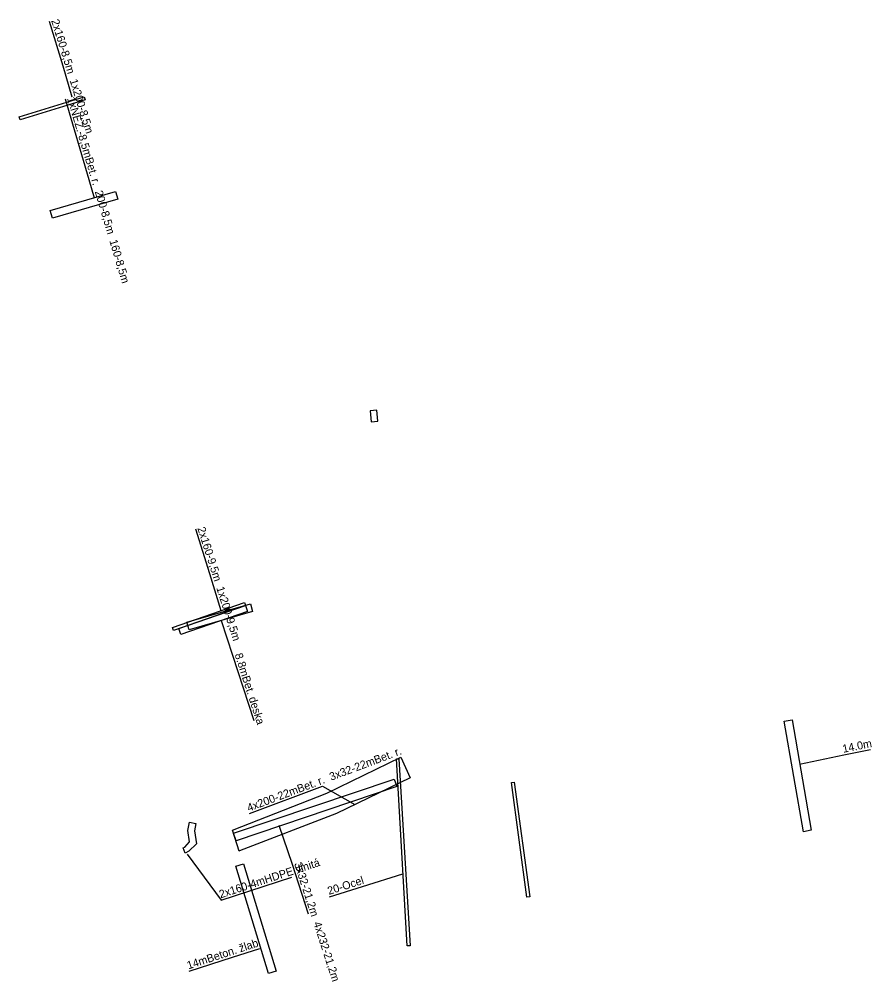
# Model space of a CAD drawing. Extents: x -740632 to -740525, y -1046807 to -1046687.
import ezdxf

# ---------------------------------------------------------------- set-up
doc = ezdxf.new("R2010")
doc.units = 0
for name, color, linetype in [('Chránička', 7, 'Continuous'), ('ST_CHRANICKA_POPIS', 7, 'Continuous'), ('ST_OBECNA_STAVBA', 7, 'Continuous')]:
    doc.layers.add(name, color=color, linetype=linetype)

msp = doc.modelspace()

# ---------------------------------------------------------------- linework, layer by layer
at = {"layer": 'Chránička'}
for points in [[(-740631.59, -1046699.489), (-740631.704, -1046699.105), (-740623.576, -1046696.612), (-740623.463, -1046696.994), (-740631.59, -1046699.489)], [(-740627.552, -1046711.796), (-740627.832, -1046710.836), (-740619.672, -1046708.458), (-740619.392, -1046709.418), (-740627.552, -1046711.796)], [(-740612.405, -1046763.312), (-740612.537, -1046762.934), (-740603.563, -1046759.817), (-740603.431, -1046760.195), (-740612.405, -1046763.312)], [(-740611.492, -1046763.814), (-740611.752, -1046763.058), (-740603.431, -1046760.195), (-740603.171, -1046760.951), (-740611.492, -1046763.814)], [(-740610.464, -1046763.249), (-740610.744, -1046762.289), (-740602.808, -1046759.977), (-740602.528, -1046760.937), (-740610.464, -1046763.249)], [(-740532.699, -1046788.285), (-740533.685, -1046788.457), (-740536.083, -1046774.664), (-740535.097, -1046774.492), (-740532.699, -1046788.285)], [(-740604.166, -1046790.844), (-740604.208, -1046790.886), (-740605.046, -1046788.265), (-740593.276, -1046783.655), (-740583.992, -1046779.129), (-740582.839, -1046781.729), (-740592.06, -1046786.171), (-740604.166, -1046790.844)], [(-740583.227, -1046802.737), (-740584.57, -1046779.371), (-740584.257, -1046779.365), (-740582.825, -1046802.71), (-740583.227, -1046802.737)], [(-740604.603, -1046789.596), (-740604.923, -1046788.648), (-740584.832, -1046781.882), (-740584.512, -1046782.83), (-740604.603, -1046789.596)], [(-740569.832, -1046782.28), (-740567.877, -1046796.585), (-740568.273, -1046796.643), (-740570.159, -1046782.321), (-740569.832, -1046782.28)], [(-740610.425, -1046787.274), (-740609.641, -1046787.429), (-740609.817, -1046788.342), (-740609.569, -1046789.974), (-740610.506, -1046790.892), (-740610.946, -1046791.122), (-740611.215, -1046790.485), (-740610.988, -1046790.389), (-740610.414, -1046789.724), (-740610.626, -1046788.32), (-740610.425, -1046787.274)], [(-740604.637, -1046792.779), (-740603.681, -1046792.487), (-740599.604, -1046805.88), (-740600.56, -1046806.172), (-740604.637, -1046792.779)]]:
    msp.add_lwpolyline(points, close=True, dxfattribs=at)
at = {"layer": 'ST_CHRANICKA_POPIS'}
for points in [[(-740627.959, -1046687.174), (-740626.237, -1046692.748), (-740625.118, -1046696.607)], [(-740625.977, -1046696.869), (-740622.989, -1046706.933), (-740622.358, -1046709.227)], [(-740609.687, -1046750.621), (-740607.921, -1046756.181), (-740606.517, -1046760.832)], [(-740606.464, -1046762.06), (-740605.032, -1046766.396), (-740602.402, -1046774.562)], [(-740534.161, -1046780.003), (-740528.652, -1046778.852), (-740525.289, -1046778.171)], [(-740602.922, -1046786.205), (-740593.799, -1046782.777), (-740589.756, -1046785.06)], [(-740599.248, -1046787.628), (-740597.593, -1046792.519), (-740595.586, -1046798.723)], [(-740610.711, -1046791.288), (-740606.461, -1046797.031), (-740597.653, -1046794.162)], [(-740592.922, -1046796.606), (-740588.804, -1046795.288), (-740583.771, -1046793.712)], [(-740610.479, -1046805.906), (-740605.065, -1046804.134), (-740601.644, -1046803.051)]]:
    msp.add_lwpolyline(points, dxfattribs=at)
at = {"layer": 'ST_OBECNA_STAVBA'}
msp.add_lwpolyline([(-740587.835, -1046735.867), (-740587.715, -1046737.233), (-740586.871, -1046737.153), (-740586.992, -1046735.787), (-740587.835, -1046735.867)], dxfattribs=at)

# ---------------------------------------------------------------- texts
at = {"layer": 'ST_CHRANICKA_POPIS'}
for s, rotation, p in [('2x160-8,5m  1x200-8,5m', 287.16939, (-740627.72, -1046687.101)), ('1xNEZ.-8,5mBet. r.  200-8,5m  160-8,5m', 286.53484, (-740625.737, -1046696.797)), ('2x160-9,5m  1x200-9,5m', 287.62351, (-740609.449, -1046750.545)), ('8.8mBet. deska', 287.84779, (-740604.794, -1046766.32)), ('14.0m', 11.44761, (-740528.702, -1046778.607)), ('4x200-22mBet. r.  3x32-22mBet. r.', 20.59621, (-740603.01, -1046785.971)), ('2x160-4mHDPE vlnitá', 18.04144, (-740606.538, -1046796.793)), ('3x32-21,2m  4x232-21,2m', 287.91982, (-740597.355, -1046792.443)), ('20-Ocel', 17.75718, (-740592.998, -1046796.368)), ('14mBeton. žlab', 18.12283, (-740610.557, -1046805.669))]:
    msp.add_text(s, height=1, rotation=rotation, dxfattribs=at).set_placement(p)

doc.saveas('drawing.dxf')
